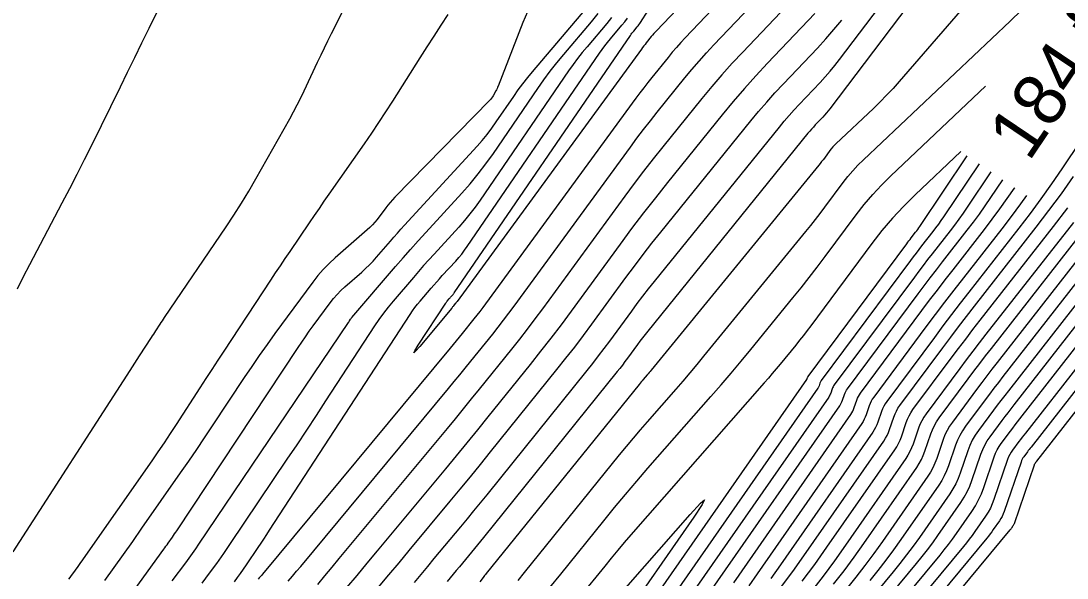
# Model space of a CAD drawing. Extents: x 7585033 to 7595090, y 547091 to 553471.
# Drawn here: x 7587379 to 7587504.7, y 548171.7 to 548238.7 of the extents above; entities that cross this region are included whole.
import ezdxf

# ---------------------------------------------------------------- set-up
doc = ezdxf.new("R2010")
doc.units = 0
for name, color, linetype in [('E_TERR_DSPLAY_GeneralTx', 7, 'Continuous'), ('E_TERR_DSPLAY_MajContour', 7, 'Continuous'), ('E_TERR_DSPLAY_MinContour', 7, 'Continuous')]:
    doc.layers.add(name, color=color, linetype=linetype)

msp = doc.modelspace()

# ---------------------------------------------------------------- linework, layer by layer
at = {"layer": 'E_TERR_DSPLAY_MajContour'}
for points in [[(7587476.77, 548255.54), (7587458.79, 548236.63), (7587458.26, 548236.06), (7587457.74, 548235.48), (7587457.23, 548234.89), (7587456.73, 548234.28), (7587454.77, 548231.86), (7587454.28, 548231.25), (7587453.81, 548230.63), (7587453.33, 548230.01), (7587452.87, 548229.38), (7587434.79, 548204.65), (7587434.46, 548204.19), (7587434.11, 548203.74), (7587433.76, 548203.29), (7587433.41, 548202.84), (7587431.98, 548201.07), (7587431.63, 548200.63), (7587431.27, 548200.19), (7587430.91, 548199.75), (7587430.55, 548199.32), (7587407.99, 548172.16), (7587407.87, 548172), (7587407.74, 548171.85), (7587407.61, 548171.7), (7587407.48, 548171.55)], [(7587517.49, 548240.94), (7587504.03, 548220.87), (7587502.79, 548219.06), (7587501.52, 548217.27), (7587500.22, 548215.51), (7587498.88, 548213.76), (7587492.87, 548206.07), (7587491.82, 548204.72), (7587490.78, 548203.36), (7587489.75, 548202), (7587488.72, 548200.62), (7587483, 548192.92), (7587482.81, 548192.64), (7587482.64, 548192.35), (7587482.49, 548192.04), (7587482.37, 548191.72), (7587481.93, 548190.43), (7587481.81, 548190.11), (7587481.66, 548189.8), (7587481.5, 548189.5), (7587481.32, 548189.21), (7587470.23, 548173.26), (7587469.06, 548171.62)], [(7587439.85, 548239.77), (7587439.29, 548238.46), (7587436.31, 548230.83), (7587436.25, 548230.68), (7587436.18, 548230.53), (7587436.11, 548230.38), (7587436.03, 548230.24), (7587435.71, 548229.67), (7587435.62, 548229.53), (7587435.53, 548229.39), (7587435.43, 548229.27), (7587435.32, 548229.15), (7587423.91, 548217.47), (7587423.62, 548217.16), (7587423.33, 548216.84), (7587423.06, 548216.51), (7587422.8, 548216.17), (7587421.76, 548214.8), (7587421.49, 548214.46), (7587421.21, 548214.14), (7587420.91, 548213.83), (7587420.59, 548213.54), (7587416.73, 548210.17), (7587416, 548209.5), (7587415.31, 548208.78), (7587414.66, 548208.04), (7587414.05, 548207.25), (7587409.49, 548201.07), (7587408.55, 548199.77), (7587407.62, 548198.45), (7587406.7, 548197.12), (7587405.8, 548195.79), (7587401.95, 548189.97), (7587401.01, 548188.55), (7587400.06, 548187.15), (7587399.1, 548185.74), (7587398.13, 548184.35), (7587393.48, 548177.68), (7587392.37, 548176.1), (7587391.26, 548174.53), (7587390.14, 548172.97), (7587389.02, 548171.41)], [(7587438.73, 548171.41), (7587439.49, 548172.35), (7587450.9, 548186.5), (7587451.72, 548187.51), (7587452.56, 548188.51), (7587453.4, 548189.5), (7587454.25, 548190.48), (7587457.68, 548194.39), (7587458.53, 548195.37), (7587459.38, 548196.36), (7587460.21, 548197.36), (7587461.04, 548198.36), (7587473.28, 548213.34), (7587473.86, 548214.06), (7587474.43, 548214.78), (7587474.99, 548215.51), (7587475.55, 548216.25), (7587477.75, 548219.22), (7587478.32, 548219.95), (7587478.91, 548220.65), (7587479.54, 548221.32), (7587480.19, 548221.97), (7587497.81, 548238.64), (7587499.17, 548239.95)], [(7587404.64, 548171.25), (7587405.01, 548171.75), (7587405.37, 548172.25), (7587405.73, 548172.76), (7587406.08, 548173.28), (7587407.48, 548175.35), (7587407.83, 548175.87), (7587408.17, 548176.38), (7587408.51, 548176.91), (7587408.85, 548177.43), (7587425.73, 548203.37), (7587426.01, 548203.79), (7587426.31, 548204.2), (7587426.62, 548204.6), (7587426.94, 548204.99), (7587428.26, 548206.52), (7587428.59, 548206.91), (7587428.93, 548207.29), (7587429.26, 548207.66), (7587429.6, 548208.04), (7587431.21, 548209.79), (7587431.58, 548210.21), (7587431.94, 548210.64), (7587432.28, 548211.09), (7587432.61, 548211.55), (7587448.49, 548234.78), (7587448.8, 548235.23), (7587449.12, 548235.66), (7587449.45, 548236.08), (7587449.8, 548236.5), (7587451.19, 548238.15), (7587451.53, 548238.56), (7587451.86, 548238.99)], [(7587421.95, 548170.59), (7587423.18, 548172.06), (7587424.41, 548173.53), (7587425.64, 548175.01), (7587430.54, 548180.91), (7587431.76, 548182.38), (7587432.98, 548183.86), (7587434.19, 548185.35), (7587435.39, 548186.84), (7587443.38, 548196.74), (7587444.45, 548198.1), (7587445.51, 548199.46), (7587446.56, 548200.84), (7587447.58, 548202.22), (7587451.66, 548207.8), (7587452.69, 548209.19), (7587453.73, 548210.57), (7587454.79, 548211.93), (7587455.87, 548213.28), (7587466.67, 548226.63), (7587467.61, 548227.78), (7587468.58, 548228.91), (7587469.57, 548230.01), (7587470.58, 548231.1), (7587474.67, 548235.4), (7587475.68, 548236.49), (7587476.66, 548237.61), (7587477.6, 548238.75)], [(7587471.28, 548145.43), (7587497.84, 548177.5), (7587497.89, 548177.56), (7587497.93, 548177.62), (7587497.98, 548177.68), (7587498.02, 548177.74), (7587498.19, 548177.99), (7587498.23, 548178.05), (7587498.27, 548178.12), (7587498.3, 548178.19), (7587498.33, 548178.26), (7587500.73, 548185.31), (7587500.74, 548185.35), (7587500.76, 548185.39), (7587500.78, 548185.43), (7587500.81, 548185.46), (7587500.91, 548185.6), (7587500.94, 548185.63), (7587500.96, 548185.67), (7587500.99, 548185.7), (7587501.01, 548185.73), (7587531.17, 548224.33)], [(7587495.52, 548220.53), (7587492.66, 548216.26), (7587492.17, 548215.54), (7587491.66, 548214.83), (7587491.14, 548214.12), (7587490.61, 548213.42), (7587488.45, 548210.66), (7587487.91, 548209.97), (7587487.37, 548209.27), (7587486.84, 548208.57), (7587486.32, 548207.87), (7587476.7, 548194.92), (7587476.62, 548194.81), (7587476.56, 548194.69), (7587476.5, 548194.57), (7587476.45, 548194.44), (7587476.27, 548193.92), (7587476.22, 548193.8), (7587476.17, 548193.67), (7587476.1, 548193.55), (7587476.03, 548193.44), (7587459, 548168.94)], [(7587468.07, 548151.08), (7587486.59, 548173.44), (7587487.25, 548174.26), (7587487.9, 548175.09), (7587488.53, 548175.94), (7587489.14, 548176.8), (7587491.89, 548180.76), (7587492.3, 548181.39), (7587492.66, 548182.05), (7587492.97, 548182.73), (7587493.24, 548183.43), (7587494.32, 548186.58), (7587494.53, 548187.14), (7587494.78, 548187.68), (7587495.08, 548188.19), (7587495.42, 548188.68), (7587496.85, 548190.61), (7587497.21, 548191.09), (7587497.57, 548191.56), (7587497.93, 548192.04), (7587498.3, 548192.51), (7587519.72, 548219.94)], [(7587476.62, 548170.96), (7587477.87, 548172.56), (7587479.08, 548174.2), (7587480.26, 548175.86), (7587486.6, 548184.99), (7587486.9, 548185.45), (7587487.16, 548185.92), (7587487.39, 548186.42), (7587487.58, 548186.93), (7587488.29, 548189.01), (7587488.49, 548189.52), (7587488.72, 548190.01), (7587488.99, 548190.48), (7587489.3, 548190.93), (7587492.78, 548195.62), (7587493.48, 548196.54), (7587494.17, 548197.46), (7587494.88, 548198.38), (7587495.59, 548199.29), (7587508.28, 548215.54)]]:
    msp.add_lwpolyline(points, dxfattribs=at)
at = {"layer": 'E_TERR_DSPLAY_MinContour'}
for points in [[(7587478.15, 548261.47), (7587455.34, 548237.48), (7587455.18, 548237.31), (7587455.02, 548237.13), (7587454.86, 548236.95), (7587454.71, 548236.77), (7587454.11, 548236.03), (7587453.96, 548235.84), (7587453.82, 548235.65), (7587453.67, 548235.46), (7587453.53, 548235.27), (7587431.37, 548204.94), (7587431.32, 548204.87), (7587431.27, 548204.8), (7587431.22, 548204.74), (7587431.16, 548204.67), (7587430.95, 548204.41), (7587430.9, 548204.34), (7587430.84, 548204.27), (7587430.79, 548204.21), (7587430.73, 548204.14), (7587426.9, 548199.53), (7587426.4, 548198.95), (7587426.2, 548198.77), (7587426.3, 548199.02), (7587426.71, 548199.67), (7587430.01, 548204.75), (7587430.06, 548204.81), (7587430.1, 548204.87), (7587430.15, 548204.93), (7587430.2, 548204.99), (7587430.39, 548205.22), (7587430.44, 548205.28), (7587430.49, 548205.33), (7587430.54, 548205.39), (7587430.59, 548205.45), (7587430.83, 548205.71), (7587430.89, 548205.77), (7587430.94, 548205.84), (7587430.99, 548205.9), (7587431.04, 548205.97), (7587452.2, 548236.92), (7587452.29, 548237.05), (7587452.39, 548237.18), (7587452.49, 548237.31), (7587452.6, 548237.44), (7587453.02, 548237.94), (7587453.13, 548238.07), (7587453.23, 548238.2), (7587453.32, 548238.33), (7587453.41, 548238.47), (7587454.33, 548239.9)], [(7587426.25, 548171.16), (7587427.05, 548172.11), (7587427.85, 548173.07), (7587428.64, 548174.03), (7587431.82, 548177.86), (7587432.62, 548178.82), (7587433.41, 548179.78), (7587434.19, 548180.74), (7587434.98, 548181.71), (7587447, 548196.62), (7587447.69, 548197.49), (7587448.38, 548198.38), (7587449.05, 548199.27), (7587449.72, 548200.17), (7587452.36, 548203.77), (7587453.02, 548204.67), (7587453.7, 548205.56), (7587454.38, 548206.44), (7587455.08, 548207.32), (7587470.1, 548225.9), (7587470.68, 548226.59), (7587471.27, 548227.28), (7587471.87, 548227.96), (7587472.49, 548228.62), (7587474.99, 548231.25), (7587475.61, 548231.92), (7587476.2, 548232.6), (7587476.78, 548233.3), (7587477.34, 548234.01), (7587498.05, 548261.38)], [(7587504.39, 548254.36), (7587484.49, 548231.39), (7587483.75, 548230.55), (7587482.98, 548229.73), (7587482.2, 548228.93), (7587481.39, 548228.15), (7587476.9, 548223.9), (7587476.71, 548223.71), (7587476.52, 548223.51), (7587476.34, 548223.29), (7587476.17, 548223.08), (7587475.51, 548222.18), (7587475.34, 548221.96), (7587475.17, 548221.74), (7587475, 548221.52), (7587474.82, 548221.31), (7587454.69, 548196.68), (7587454.58, 548196.53), (7587454.46, 548196.39), (7587454.33, 548196.25), (7587454.21, 548196.11), (7587453.72, 548195.54), (7587453.6, 548195.4), (7587453.48, 548195.26), (7587453.36, 548195.12), (7587453.24, 548194.97), (7587434.89, 548172.23), (7587434.79, 548172.1), (7587434.69, 548171.98), (7587434.59, 548171.86), (7587434.5, 548171.74), (7587434.11, 548171.25)], [(7587411.1, 548171.31), (7587411.6, 548171.9), (7587412.09, 548172.5), (7587412.59, 548173.09), (7587430.36, 548194.49), (7587431.03, 548195.3), (7587431.69, 548196.11), (7587432.36, 548196.93), (7587433.02, 548197.74), (7587435.66, 548201.02), (7587436.31, 548201.84), (7587436.96, 548202.67), (7587437.59, 548203.51), (7587438.22, 548204.35), (7587452.21, 548223.5), (7587452.99, 548224.56), (7587453.79, 548225.61), (7587454.61, 548226.65), (7587455.43, 548227.69), (7587458.76, 548231.8), (7587459.6, 548232.82), (7587460.46, 548233.82), (7587461.34, 548234.81), (7587462.24, 548235.78), (7587475.39, 548249.61)], [(7587378.04, 548174.85), (7587392.1, 548196.64), (7587392.38, 548197.07), (7587392.66, 548197.51), (7587392.95, 548197.95), (7587393.23, 548198.39), (7587394.67, 548200.61), (7587394.8, 548200.81), (7587394.93, 548201.01), (7587395.06, 548201.21), (7587395.19, 548201.41), (7587395.71, 548202.21), (7587395.84, 548202.4), (7587395.97, 548202.6), (7587396.11, 548202.8), (7587396.24, 548203), (7587403.62, 548213.9), (7587404.55, 548215.32), (7587405.46, 548216.75), (7587406.34, 548218.21), (7587407.19, 548219.68), (7587411.28, 548226.89), (7587411.74, 548227.72), (7587412.18, 548228.56), (7587412.61, 548229.41), (7587413.02, 548230.27), (7587414.62, 548233.71), (7587415.03, 548234.57), (7587415.44, 548235.43), (7587415.85, 548236.28), (7587416.28, 548237.13), (7587421.41, 548247.42)], [(7587378.55, 548206.44), (7587379.3, 548207.92), (7587380.06, 548209.39), (7587383.95, 548216.79), (7587384.85, 548218.52), (7587385.74, 548220.25), (7587386.62, 548221.98), (7587387.48, 548223.73), (7587390.94, 548230.75), (7587391.8, 548232.51), (7587392.66, 548234.26), (7587393.52, 548236.01), (7587394.38, 548237.77), (7587399.16, 548247.52)], [(7587474.04, 548243.7), (7587465.7, 548234.92), (7587464.42, 548233.56), (7587463.18, 548232.17), (7587461.97, 548230.76), (7587460.78, 548229.32), (7587456.09, 548223.52), (7587454.93, 548222.06), (7587453.78, 548220.59), (7587452.65, 548219.11), (7587451.54, 548217.61), (7587441.64, 548204.06), (7587440.73, 548202.83), (7587439.81, 548201.6), (7587438.86, 548200.39), (7587437.91, 548199.19), (7587434.05, 548194.41), (7587433.09, 548193.22), (7587432.12, 548192.03), (7587431.15, 548190.84), (7587430.17, 548189.66), (7587417.18, 548174.03), (7587416.32, 548172.99), (7587415.46, 548171.96), (7587414.6, 548170.93)], [(7587487.67, 548243.31), (7587476.16, 548228.1), (7587475.96, 548227.84), (7587475.75, 548227.59), (7587475.53, 548227.34), (7587475.31, 548227.1), (7587474.4, 548226.15), (7587474.18, 548225.9), (7587473.96, 548225.66), (7587473.74, 548225.41), (7587473.53, 548225.16), (7587454.29, 548201.36), (7587453.97, 548200.96), (7587453.66, 548200.56), (7587453.35, 548200.15), (7587453.05, 548199.75), (7587451.85, 548198.11), (7587451.55, 548197.7), (7587451.24, 548197.29), (7587450.93, 548196.89), (7587450.62, 548196.5), (7587434.56, 548176.58), (7587434.2, 548176.14), (7587433.84, 548175.69), (7587433.48, 548175.25), (7587433.11, 548174.81), (7587431.65, 548173.04), (7587431.28, 548172.6), (7587430.91, 548172.16), (7587430.55, 548171.73), (7587430.18, 548171.29)], [(7587392.7, 548170.4), (7587396.14, 548175.14), (7587396.27, 548175.33), (7587396.4, 548175.51), (7587396.54, 548175.69), (7587396.67, 548175.88), (7587397.19, 548176.62), (7587397.31, 548176.81), (7587397.44, 548177), (7587397.57, 548177.19), (7587397.7, 548177.37), (7587412.27, 548199.39), (7587412.71, 548200.05), (7587413.16, 548200.7), (7587413.62, 548201.35), (7587414.09, 548201.99), (7587416.13, 548204.77), (7587416.54, 548205.29), (7587416.97, 548205.78), (7587417.42, 548206.25), (7587417.91, 548206.7), (7587419.92, 548208.46), (7587420.39, 548208.88), (7587420.85, 548209.33), (7587421.29, 548209.79), (7587421.71, 548210.26), (7587423.37, 548212.2), (7587423.79, 548212.68), (7587424.21, 548213.16), (7587424.64, 548213.64), (7587425.06, 548214.11), (7587433.78, 548223.61), (7587434.4, 548224.3), (7587434.99, 548225.02), (7587435.55, 548225.76), (7587436.09, 548226.52), (7587438.19, 548229.59), (7587438.73, 548230.36), (7587439.28, 548231.1), (7587439.86, 548231.84), (7587440.45, 548232.55), (7587447.39, 548240.76)], [(7587430.26, 548239.42), (7587429.41, 548238.13), (7587428.57, 548236.84), (7587427.73, 548235.54), (7587426.91, 548234.24), (7587423.62, 548229.02), (7587422.78, 548227.72), (7587421.94, 548226.43), (7587421.08, 548225.15), (7587420.2, 548223.88), (7587415.97, 548217.84), (7587415.38, 548216.98), (7587414.79, 548216.12), (7587414.2, 548215.27), (7587413.61, 548214.4), (7587411.28, 548210.95), (7587410.7, 548210.09), (7587410.12, 548209.22), (7587409.54, 548208.36), (7587408.97, 548207.49), (7587403.35, 548198.97), (7587402.63, 548197.87), (7587401.91, 548196.77), (7587401.19, 548195.67), (7587400.48, 548194.57), (7587397.62, 548190.15), (7587396.91, 548189.05), (7587396.18, 548187.96), (7587395.44, 548186.87), (7587394.69, 548185.79), (7587386.46, 548173.98), (7587386.3, 548173.76), (7587386.14, 548173.54), (7587385.98, 548173.32), (7587385.82, 548173.09), (7587385.18, 548172.21), (7587385.02, 548171.99), (7587384.86, 548171.77), (7587384.7, 548171.54)], [(7587397.14, 548171.35), (7587398.78, 548173.53), (7587399.19, 548174.07), (7587399.58, 548174.62), (7587399.98, 548175.18), (7587400.36, 548175.74), (7587418.34, 548202.42), (7587418.37, 548202.46), (7587418.4, 548202.51), (7587418.43, 548202.56), (7587418.47, 548202.61), (7587418.59, 548202.81), (7587418.63, 548202.85), (7587418.66, 548202.9), (7587418.7, 548202.95), (7587418.73, 548202.99), (7587424, 548209.13), (7587424.89, 548210.17), (7587425.79, 548211.19), (7587426.7, 548212.21), (7587427.62, 548213.22), (7587431.96, 548217.95), (7587432.96, 548219.09), (7587433.93, 548220.26), (7587434.85, 548221.47), (7587435.74, 548222.71), (7587441.07, 548230.52), (7587441.82, 548231.57), (7587442.58, 548232.61), (7587443.38, 548233.62), (7587444.2, 548234.62), (7587447.53, 548238.55), (7587448.34, 548239.55)], [(7587449.94, 548239.06), (7587449.36, 548238.35), (7587447, 548235.56), (7587446.42, 548234.85), (7587445.85, 548234.13), (7587445.31, 548233.4), (7587444.78, 548232.65), (7587434.17, 548217.13), (7587433.57, 548216.28), (7587432.93, 548215.45), (7587432.27, 548214.65), (7587431.58, 548213.87), (7587428.61, 548210.63), (7587427.98, 548209.94), (7587427.36, 548209.24), (7587426.74, 548208.54), (7587426.13, 548207.83), (7587423.69, 548204.98), (7587423.09, 548204.26), (7587422.52, 548203.52), (7587421.97, 548202.77), (7587421.45, 548201.99), (7587415.58, 548192.98), (7587414.43, 548191.21), (7587413.27, 548189.46), (7587412.11, 548187.7), (7587410.94, 548185.96), (7587404.13, 548175.86), (7587403.3, 548174.65), (7587402.46, 548173.45), (7587401.6, 548172.26), (7587400.73, 548171.09)], [(7587474.36, 548239.55), (7587468.67, 548233.57), (7587467.27, 548232.06), (7587465.89, 548230.53), (7587464.55, 548228.96), (7587463.24, 548227.37), (7587456.66, 548219.24), (7587455.2, 548217.41), (7587453.77, 548215.57), (7587452.35, 548213.71), (7587450.96, 548211.83), (7587445.07, 548203.77), (7587443.87, 548202.14), (7587442.65, 548200.54), (7587441.41, 548198.94), (7587440.16, 548197.37), (7587435.09, 548191.08), (7587433.82, 548189.51), (7587432.55, 548187.95), (7587431.27, 548186.39), (7587429.98, 548184.83), (7587421.78, 548174.96), (7587420.55, 548173.48), (7587419.32, 548172.01), (7587418.09, 548170.54)], [(7587442.53, 548170.54), (7587443.83, 548172.15), (7587449.01, 548178.57), (7587450.31, 548180.17), (7587451.63, 548181.75), (7587452.96, 548183.33), (7587454.31, 548184.88), (7587461.88, 548193.52), (7587463.1, 548194.92), (7587464.3, 548196.33), (7587465.5, 548197.75), (7587466.68, 548199.18), (7587471.73, 548205.37), (7587472.72, 548206.59), (7587473.69, 548207.82), (7587474.65, 548209.07), (7587475.59, 548210.32), (7587479.33, 548215.36), (7587480.3, 548216.6), (7587481.31, 548217.79), (7587482.37, 548218.93), (7587483.49, 548220.03), (7587494.86, 548230.8)], [(7587528.3, 548223.23), (7587500.34, 548187.43), (7587500.22, 548187.29), (7587500.11, 548187.14), (7587500, 548187), (7587499.89, 548186.85), (7587499.46, 548186.27), (7587499.36, 548186.12), (7587499.27, 548185.96), (7587499.19, 548185.8), (7587499.13, 548185.63), (7587497.1, 548179.69), (7587496.99, 548179.39), (7587496.86, 548179.1), (7587496.7, 548178.83), (7587496.53, 548178.56), (7587495.8, 548177.51), (7587495.61, 548177.25), (7587495.42, 548176.99), (7587495.23, 548176.74), (7587495.03, 548176.49), (7587470.48, 548146.84)], [(7587491.91, 548222.96), (7587486.4, 548217.75), (7587485.01, 548216.37), (7587483.69, 548214.94), (7587482.42, 548213.46), (7587481.22, 548211.91), (7587473.87, 548202.02), (7587473.43, 548201.43), (7587472.98, 548200.84), (7587472.52, 548200.27), (7587472.06, 548199.69), (7587470.2, 548197.41), (7587469.73, 548196.84), (7587469.25, 548196.28), (7587468.78, 548195.72), (7587468.29, 548195.17), (7587452.27, 548176.88), (7587451.47, 548175.96), (7587450.68, 548175.02), (7587449.89, 548174.08), (7587449.12, 548173.13), (7587446.05, 548169.33)], [(7587453.38, 548166.78), (7587473.38, 548195.55), (7587473.4, 548195.58), (7587473.42, 548195.61), (7587473.43, 548195.64), (7587473.44, 548195.67), (7587473.49, 548195.8), (7587473.5, 548195.83), (7587473.51, 548195.86), (7587473.53, 548195.89), (7587473.55, 548195.92), (7587485.41, 548211.88), (7587485.54, 548212.05), (7587485.67, 548212.23), (7587485.8, 548212.4), (7587485.93, 548212.57), (7587486.47, 548213.25), (7587486.6, 548213.43), (7587486.73, 548213.6), (7587486.86, 548213.78), (7587486.98, 548213.96), (7587492.67, 548222.45)], [(7587525.44, 548222.13), (7587499.66, 548189.12), (7587499.46, 548188.87), (7587499.26, 548188.62), (7587499.07, 548188.36), (7587498.88, 548188.1), (7587498.11, 548187.07), (7587497.93, 548186.81), (7587497.77, 548186.53), (7587497.64, 548186.25), (7587497.52, 548185.95), (7587495.88, 548181.13), (7587495.68, 548180.6), (7587495.45, 548180.09), (7587495.18, 548179.6), (7587494.87, 548179.13), (7587493.58, 548177.27), (7587493.25, 548176.81), (7587492.92, 548176.36), (7587492.57, 548175.91), (7587492.21, 548175.47), (7587469.68, 548148.26)], [(7587494.1, 548221.49), (7587489.82, 548215.11), (7587489.51, 548214.66), (7587489.2, 548214.21), (7587488.87, 548213.77), (7587488.54, 548213.34), (7587487.19, 548211.61), (7587486.85, 548211.18), (7587486.52, 548210.75), (7587486.19, 548210.31), (7587485.86, 548209.87), (7587475.12, 548195.42), (7587475.08, 548195.35), (7587475.03, 548195.28), (7587475, 548195.2), (7587474.97, 548195.12), (7587474.86, 548194.8), (7587474.83, 548194.72), (7587474.79, 548194.64), (7587474.75, 548194.57), (7587474.7, 548194.5), (7587456.19, 548167.86)], [(7587468.88, 548149.67), (7587489.4, 548174.45), (7587489.91, 548175.08), (7587490.41, 548175.72), (7587490.89, 548176.37), (7587491.36, 548177.03), (7587493.21, 548179.7), (7587493.65, 548180.38), (7587494.04, 548181.08), (7587494.37, 548181.8), (7587494.66, 548182.56), (7587495.92, 548186.27), (7587496.08, 548186.69), (7587496.28, 548187.1), (7587496.51, 548187.5), (7587496.76, 548187.88), (7587497.86, 548189.35), (7587498.14, 548189.72), (7587498.42, 548190.09), (7587498.7, 548190.46), (7587498.98, 548190.82), (7587522.58, 548221.03)], [(7587461.8, 548170.02), (7587477.35, 548192.38), (7587477.45, 548192.54), (7587477.54, 548192.7), (7587477.62, 548192.87), (7587477.69, 548193.05), (7587477.93, 548193.76), (7587478, 548193.94), (7587478.08, 548194.11), (7587478.17, 548194.27), (7587478.28, 548194.42), (7587486.78, 548205.86), (7587487.5, 548206.83), (7587488.23, 548207.79), (7587488.96, 548208.75), (7587489.7, 548209.7), (7587492.67, 548213.51), (7587493.41, 548214.47), (7587494.13, 548215.44), (7587494.82, 548216.42), (7587495.51, 548217.42), (7587496.95, 548219.56)], [(7587470.36, 548170.66), (7587471.72, 548172.48), (7587473.03, 548174.34), (7587482.64, 548188.16), (7587482.85, 548188.49), (7587483.04, 548188.83), (7587483.2, 548189.18), (7587483.34, 548189.55), (7587483.85, 548191.04), (7587483.99, 548191.41), (7587484.16, 548191.76), (7587484.35, 548192.1), (7587484.58, 548192.43), (7587489.74, 548199.37), (7587490.68, 548200.63), (7587491.63, 548201.89), (7587492.59, 548203.14), (7587493.55, 548204.38), (7587500.95, 548213.85), (7587502.49, 548215.85), (7587503.99, 548217.88), (7587505.45, 548219.94)], [(7587464.61, 548171.1), (7587478.67, 548191.33), (7587478.8, 548191.53), (7587478.92, 548191.74), (7587479.02, 548191.95), (7587479.1, 548192.17), (7587479.41, 548193.08), (7587479.5, 548193.31), (7587479.6, 548193.52), (7587479.72, 548193.73), (7587479.85, 548193.92), (7587487.23, 548203.86), (7587488.15, 548205.09), (7587489.08, 548206.31), (7587490.02, 548207.53), (7587490.96, 548208.75), (7587494.74, 548213.59), (7587495.68, 548214.81), (7587496.59, 548216.05), (7587497.48, 548217.3), (7587498.35, 548218.57), (7587498.37, 548218.6)], [(7587516.86, 548218.84), (7587497.62, 548194.21), (7587497.17, 548193.63), (7587496.72, 548193.04), (7587496.27, 548192.45), (7587495.83, 548191.86), (7587494.03, 548189.43), (7587493.63, 548188.85), (7587493.28, 548188.25), (7587492.99, 548187.62), (7587492.73, 548186.97), (7587491.83, 548184.3), (7587491.58, 548183.65), (7587491.29, 548183.02), (7587490.95, 548182.41), (7587490.57, 548181.82), (7587486.92, 548176.56), (7587486.17, 548175.5), (7587485.39, 548174.46), (7587484.59, 548173.43), (7587483.78, 548172.42), (7587467.27, 548152.49)], [(7587499.77, 548217.66), (7587499.06, 548216.66), (7587497.95, 548215.16), (7587496.81, 548213.68), (7587492.2, 548207.77), (7587491.06, 548206.31), (7587489.93, 548204.84), (7587488.81, 548203.36), (7587487.71, 548201.88), (7587481.43, 548193.42), (7587481.26, 548193.18), (7587481.12, 548192.93), (7587480.99, 548192.67), (7587480.89, 548192.4), (7587480.51, 548191.3), (7587480.41, 548191.03), (7587480.29, 548190.77), (7587480.15, 548190.51), (7587479.99, 548190.27), (7587467.42, 548172.18), (7587466.41, 548170.76)], [(7587514, 548217.74), (7587496.94, 548195.9), (7587496.41, 548195.21), (7587495.87, 548194.51), (7587495.34, 548193.81), (7587494.82, 548193.11), (7587492.45, 548189.93), (7587492.09, 548189.39), (7587491.76, 548188.84), (7587491.49, 548188.25), (7587491.25, 548187.65), (7587490.41, 548185.18), (7587490.18, 548184.57), (7587489.91, 548183.99), (7587489.6, 548183.42), (7587489.25, 548182.87), (7587484.7, 548176.33), (7587483.8, 548175.07), (7587482.88, 548173.83), (7587481.94, 548172.61), (7587480.96, 548171.41)], [(7587472.85, 548171.3), (7587474.35, 548173.33), (7587475.82, 548175.39), (7587483.96, 548187.1), (7587484.2, 548187.47), (7587484.41, 548187.86), (7587484.6, 548188.26), (7587484.76, 548188.68), (7587485.33, 548190.37), (7587485.49, 548190.78), (7587485.68, 548191.18), (7587485.9, 548191.56), (7587486.15, 548191.93), (7587490.75, 548198.12), (7587491.61, 548199.27), (7587492.48, 548200.41), (7587493.35, 548201.55), (7587494.23, 548202.68), (7587503.02, 548213.93), (7587504.76, 548216.2)], [(7587511.14, 548216.64), (7587496.27, 548197.6), (7587495.64, 548196.8), (7587495.02, 548195.99), (7587494.41, 548195.18), (7587493.8, 548194.36), (7587490.88, 548190.43), (7587490.54, 548189.94), (7587490.24, 548189.42), (7587489.99, 548188.89), (7587489.77, 548188.33), (7587489, 548186.05), (7587488.79, 548185.49), (7587488.54, 548184.95), (7587488.25, 548184.43), (7587487.93, 548183.93), (7587482.48, 548176.09), (7587481.44, 548174.63), (7587480.37, 548173.2), (7587479.28, 548171.78), (7587478.15, 548170.39)], [(7587505.42, 548214.44), (7587494.91, 548200.99), (7587494.11, 548199.97), (7587493.33, 548198.94), (7587492.54, 548197.9), (7587491.77, 548196.87), (7587487.73, 548191.43), (7587487.45, 548191.02), (7587487.2, 548190.59), (7587486.99, 548190.15), (7587486.81, 548189.69), (7587486.17, 548187.8), (7587485.99, 548187.34), (7587485.79, 548186.89), (7587485.55, 548186.46), (7587485.28, 548186.04), (7587478.04, 548175.62), (7587476.72, 548173.76), (7587475.36, 548171.93), (7587473.96, 548170.13)], [(7587450.22, 548168.88), (7587459.38, 548179.33), (7587460.62, 548180.69), (7587461.1, 548181.08), (7587460.83, 548180.52), (7587459.81, 548178.99), (7587450.58, 548165.7)]]:
    msp.add_lwpolyline(points, dxfattribs=at)

# ---------------------------------------------------------------- texts
at = {"layer": 'E_TERR_DSPLAY_GeneralTx'}
msp.add_text('184 ft', height=6.3, rotation=55.9552, dxfattribs=at).set_placement((7587500.07, 548221.63))

doc.saveas('drawing.dxf')
